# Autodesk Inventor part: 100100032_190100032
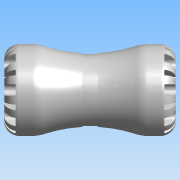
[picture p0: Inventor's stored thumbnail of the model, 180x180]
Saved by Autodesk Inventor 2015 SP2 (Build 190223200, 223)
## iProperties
Created: 2016-12
Part Number: 100100032_190100032
Material: PVC-Piping
Description: PLASSON COUPLER 32X32 SERIES 1
Document SubType Name: Modeling
Designer: KIM
Mass: 95.2094 g
Surface Area: 200.83 cm^2
Volume: 68.0067 cm^3
Density: 1.4 g/cm^3
Appearance: Smooth - White
ILogicFactory: False
Author: KIM
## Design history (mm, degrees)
derived "1001.ipt"
feature "Solid1::1001.ipt"
tag "TaggingFeature1"
body "Solid1"
other parameters: "d2" = 53, "d4" = 2.66667, "d11" = 7.2, "d13" = 7.2, "d14" = 0, "d16" = 360 deg, "d18" = 8 deg, "d19" = 0.64, "d20" = 8 deg, "d21" = 0.64, "d23" = 0, "d25" = 360 deg, "d27" = 23.2, "d28" = 8, "d29" = 9.6, "d30" = 9.6, "d31" = 0, "d33" = 0, "d37" = 21.6, "d38" = 0.58, "d43" = 4, "d44" = 32, "d45" = 21.6, "d46" = 46.4, "d47" = 58, "d48" = 108, "d50" = 360 deg, "d54" = 0.513, "d_" = 32, "E_" = 58, "H_" = 108, "l_" = 53, "d42" = 58, "d52" = 9
